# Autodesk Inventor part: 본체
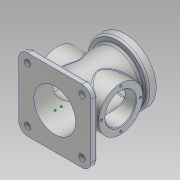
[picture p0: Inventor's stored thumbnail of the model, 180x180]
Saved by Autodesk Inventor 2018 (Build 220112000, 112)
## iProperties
Created: 2021-03
Part Number: 본체
Material: 알루미늄 6061
Document SubType Name: 모델링
Designer: home
Density: 2.7 g/cm^3
Appearance: 알루미늄 - 평지
Mass: 830.882 g
Surface Area: 866.518 cm^2
Volume: 307.734 cm^3
Author: home
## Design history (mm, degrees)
sketch "스케치2"
  geometry: L1 (57, -57)-(-57, -57); L2 (-57, -57)-(-57, 57); L3 (-57, 57)-(57, 57); L4 (57, 57)-(57, -57); 1 further point
  constraints: 8 end point, 2 parallel, 1 horizontal, 1 perpendicular
  dimensions: "d0" = 114 distance of L1.end L2.end; "d1" = 114 distance of L1.start L1.end; "d2" = 57 distance from line of point (0, 0) L2; "d17" = 57 distance from line of point (0, 0) L1
extrude "돌출1" new body sketch "스케치2" distance "d4" = 10; taper "d5" = 0 deg
node "작업 평면1"
sketch "스케치3"
  geometry: L1 (0, 0)-(38, 0); L2 (38, 0)-(38, 98); L3 (0, 63.493)-(0, 0); L4 (38, 98)-(49, 98); L5 (49, 98)-(49, 111); L6 (49, 111)-(0, 111); L7 (0, 111)-(0, 63.493); L8 (57, 0)-(-57, 0) reference
  constraints: 14 end point, 3 parallel, 2 horizontal, 2 perpendicular
  dimensions: "d7" = 49 distance between parallel lines of L7 L5; "d8" = 111 distance between parallel lines of L8 L6; "d9" = 13 distance between parallel lines of L4 L6; "d10" = 38 distance between parallel lines of L3 L2; "d18" = 63.4927 distance from line of L3.start L8
revolve "회전1" sketch "스케치3" stored, may be unused: angle "d11" = 90 deg
sketch "스케치4"
  geometry: L1 (-50, 89)-(50, 89); L2 (50, 89)-(50, 54); L3 (50, 54)-(-50, 54); L4 (-50, 54)-(-50, 89); L5 (57, 0)-(-57, 0) reference; 1 further point
  constraints: 8 end point, 2 parallel, 1 horizontal, 1 perpendicular
  dimensions: "d12" = 54 distance between parallel lines of L5 L3; "d13" = 35 distance between parallel lines of L3 L1; "d14" = 50 distance from line of L2 point (0, 0); "d15" = 100 distance between parallel lines of L4 L2
revolve "회전2" sketch "스케치4" stored, may be unused: angle "d16" = 90 deg
sketch "스케치5"
  geometry: L1 (0, 111)-(37, 111); L2 (37, 111)-(37, 104); L3 (37, 104)-(33, 104); L4 (0, 0)-(0, 165.381); L5 (79.8, 111)-(-79.8, 111) reference; L6 (33, 104)-(33, 0); L7 (33, 0)-(0, 0); L8 (0, 0)-(0, 104); L9 (-57, 0)-(57, 0) reference
  constraints: 14 end point, 2 parallel, 2 point on line, 1 horizontal, 1 perpendicular, 1 vertical
  dimensions: "d19" = 37 distance between parallel lines of L4 L2; "d20" = 0 distance between parallel lines of L5 L1; "d21" = 7 distance between parallel lines of L3 L1; "d22" = 33 distance between parallel lines of L4 L6; "d23" = 0 distance between parallel lines of L7 L9
revolve "회전3" sketch "스케치5" stored, may be unused: angle "d24" = 90 deg
sketch "스케치6"
  geometry: L1 (-50, 78)-(50, 78); L2 (50, 78)-(50, 54); L3 (50, 54)-(-50, 54); L4 (-50, 54)-(-50, 78); L5 (50, 19)-(50, 89) reference; L6 (-50, 19)-(-50, 89) reference; 1 further point
  constraints: 8 end point, 2 parallel, 1 horizontal, 1 perpendicular
  dimensions: "d25" = 54 distance from line of point (0, 0) L3; "d26" = 24 distance between parallel lines of L3 L1; "d27" = 0 distance between parallel lines of L5 L2; "d28" = 0 distance between parallel lines of L6 L4
revolve "회전4" sketch "스케치6" stored, may be unused: angle "d29" = 90 deg
node "작업 평면2"
sketch "스케치10"
  geometry: C1 r 42 at (0, 0); 2 further points
  constraints: 1 centre point, 1 coincident
  dimensions: "d47" = 42 radius of C1
hole "구멍1" sketch "스케치10" at (-42, 0) diameter "d48" = 3.459; stored, may be unused: countersink angle "d52" = 90 deg, drill point angle "d54" = 118 deg; dims "d49" = 6, "d50" = 4, "d51" = 2, "d53" = 8
sketch "스케치11"
  geometry: C1 r 24 at (0, 0) reference; C2 r 35 at (0, 0) reference; C3 r 31 at (0, 0); 2 further points
  constraints: 1 centre point, 1 coincident
  dimensions: "d59" = 62 diameter of C3
hole "구멍2" sketch "스케치11" at (31, 0) diameter "d60" = 3.459; stored, may be unused: countersink angle "d64" = 90 deg, drill point angle "d66" = 118 deg; dims "d61" = 6, "d62" = 4, "d63" = 2, "d65" = 8
sketch "스케치12"
  geometry: 1 further point
fillet "모깎기3" dims "d70" = 14
sketch "스케치13"
  geometry: L1 (-43, -57)-(43, -57) reference; L2 (57, -43)-(57, 43) reference; L3 (43, 57)-(-43, 57) reference; L4 (-57, 43)-(-57, -43) reference; C1 r 38 at (0, 0) reference; C2 r 5 at (-43, 43); C3 r 5 at (43, 43); C4 r 5 at (43, -43); C5 r 5 at (-43, -43); A1 r 14 centre (-43, -43) between (-57, -43) and (-43, -57) reference; A2 r 14 centre (43, -43) between (43, -57) and (57, -43) reference; A3 r 14 centre (43, 43) between (57, 43) and (43, 57) reference; A4 r 14 centre (-43, 43) between (-43, 57) and (-57, 43) reference; A5 r 14 centre (-43, -43) between (-57, -43) and (-43, -57) reference; 1 further point
  constraints: 4 centre point, 4 coincident, 1 end point
  dimensions: "d71" = 5 radius of C2; "d72" = 5 radius of C3; "d73" = 5 radius of C4; "d74" = 5 radius of C5
extrude "돌출3" cut sketch "스케치13" stored distance "d75" = 23; taper "d76" = 0 deg
fillet "모깎기4" dims "d77" = 3
node "작업 평면3"
sketch "스케치18"
  geometry: L1 (0, 41)-(0, 67); L2 (7, 41)-(7, 70); L3 (-7, 70)-(-7, 41); L4 (-43, 0)-(43, 0) reference; A1 r 7 centre (0, 41) between (-7, 41) and (7, 41); A2 r 7 centre (0, 70) between (7, 70) and (-7, 70); 2 further points
  constraints: 8 end point, 4 point on circle, 4 tangent, 2 centre point, 2 parallel, 1 midpoint, 1 vertical
  dimensions: "d91" = 14 distance between parallel lines of L3 L2; "d92" = 54 distance from line of L4 point (0, 54); "d97" = 36 distance from line of L4.end L2; "d98" = 70 distance from line of L2.end L4; "d99" = 41 distance from line of L2.start L4
extrude "돌출5" join sketch "스케치18" stored distance "d100" = 14; taper "d101" = 15 deg
sketch "스케치19"
  geometry: L1 (-7, 41)-(-7, 70) reference; L2 (7, 70)-(7, 41) reference; A1 r 7 centre (0, 41) between (-7, 41) and (7, 41) reference; A2 r 7 centre (0, 70) between (7, 70) and (-7, 70) reference; 3 further points
  constraints: 2 coincident
  node "투영된 루프5"
sketch "스케치20"
  geometry: 1 further point
hole "구멍3" sketch "스케치19" diameter "d102" = 4.459; stored, may be unused: countersink angle "d106" = 90 deg, drill point angle "d108" = 118 deg; dims "d103" = 8, "d104" = 4, "d105" = 2, "d107" = 10
chamfer "모따기1" distance "d109" = 1; stored, may be unused: second distance "d110" = 2, angle "d111" = 45 deg
fillet "모깎기6" dims "d112" = 3
sketch "스케치21" dims "d113" = 50
  geometry: L1 (0, 0)-(0, 50); 1 further point
  constraints: 2 end point, 1 coincident, 1 vertical, 1 vertical alignment, 2 other
feature "엠보싱1" sketch "스케치21" dims "d0" = 114, "d1" = 114, "d2" = 57, "d17" = 57, "d114" = 0.5, "d115" = 0
chamfer "모따기2" distance "d116" = 1; stored, may be unused: second distance "d117" = 2, angle "d118" = 45 deg
node "솔리드1"
pattern_circular "원형 패턴1" dims angle "d56" = 360 deg
pattern_circular "원형 패턴2" dims angle "d68" = 360 deg
mirror "미러1"
node "투영된 루프2"
node "투영된 루프3"
other parameters: "d6" = -111, "K계수" = 4.4, "BendRadius" = 0.5 (derived), "BendReliefWidth" = 0.5 (derived), "BendReliefDepth" = 0.25 (derived), "CornerReliefSize" = 2 (derived), "SeamGap" = 0.01, "MinimumRemnant" = 1 (derived), "TransitionRadius" = 0.5 (= BendRadius), "d30" = -54, "d90" = -55
